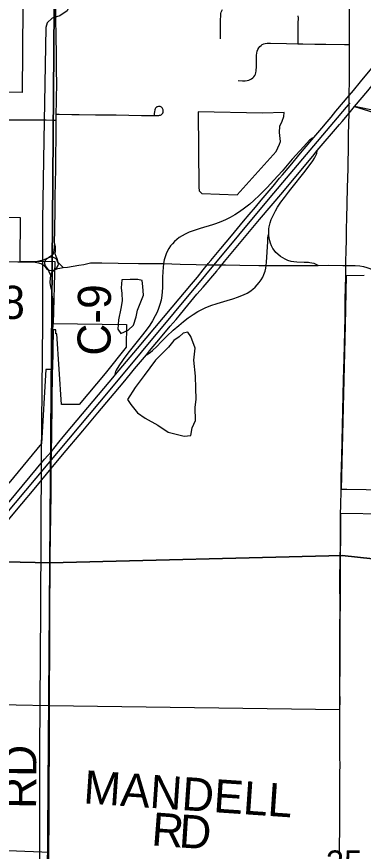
# Model space of a CAD drawing. Extents: x 0 to 34, y 0 to 22.
# Drawn here: x 6.448 to 7.043, y 18.383 to 19.815 of the extents above; entities that cross this region are included whole.
import ezdxf

# ---------------------------------------------------------------- set-up
doc = ezdxf.new("R2010")
doc.units = 0
for name, color, linetype in [('GM_X_City_Street', 7, 'Continuous'), ('GM_X_Corporation', 7, 'Continuous'), ('GM_X_County_Road', 7, 'Continuous'), ('GM_X_County_Road_Text', 7, 'Continuous'), ('GM_X_Interchange_Ramps', 7, 'Continuous'), ('GM_X_Interstate_Route', 7, 'Continuous'), ('GM_X_Minor_Lake', 7, 'Continuous'), ('GM_X_Minor_River', 7, 'Continuous'), ('GM_X_Section_Text', 7, 'Continuous'), ('GM_X_Township_Road', 7, 'Continuous'), ('GM_X_Township_Road_Text', 7, 'Continuous'), ('SH_Text', 7, 'Continuous')]:
    doc.layers.add(name, color=color, linetype=linetype)

msp = doc.modelspace()

# ---------------------------------------------------------------- linework, layer by layer
at = {"layer": 'GM_X_City_Street'}
for points in [[(6.7975, 19.7773), (6.7975, 19.7866), (6.7977, 19.809), (6.7979, 19.817), (6.7983, 19.8206), (6.7989, 19.8228), (6.8011, 19.8273)], [(6.9305, 19.8169), (6.9307, 19.8126), (6.9306, 19.8043), (6.9306, 19.7954), (6.9305, 19.7802), (6.9304, 19.7688)], [(6.828, 19.7055), (6.8354, 19.7052), (6.8399, 19.7052), (6.8431, 19.7056), (6.8462, 19.7064), (6.8486, 19.7073), (6.8509, 19.7086), (6.853, 19.7102), (6.8549, 19.7121), (6.8564, 19.7142), (6.8576, 19.7166), (6.8583, 19.7191), (6.8589, 19.7223), (6.8592, 19.7298), (6.8593, 19.7398), (6.8594, 19.7491), (6.8598, 19.7527), (6.8606, 19.7562), (6.8617, 19.759), (6.8631, 19.7616), (6.8649, 19.7639), (6.8671, 19.7659), (6.869, 19.7673), (6.8717, 19.7685), (6.8745, 19.7693), (6.8775, 19.7697), (6.8836, 19.7698), (6.911, 19.7693), (6.9304, 19.7688), (6.939, 19.7686), (6.9595, 19.7682), (6.9782, 19.7679), (7.0105, 19.7674), (7.019, 19.7673)], [(6.5157, 19.6478), (6.5203, 19.6478), (6.5425, 19.6475), (6.5549, 19.6474), (6.5829, 19.6469), (6.6186, 19.6466), (6.6403, 19.6463), (6.6621, 19.6458), (6.6823, 19.6456), (6.6884, 19.6455), (6.6915, 19.6457), (6.6929, 19.646), (6.6943, 19.6464), (6.6955, 19.647), (6.6967, 19.6478), (6.6976, 19.6488), (6.6984, 19.6499), (6.6989, 19.6512), (6.6992, 19.6525), (6.6993, 19.6539), (6.6991, 19.6552), (6.6987, 19.6566), (6.698, 19.6578), (6.6972, 19.6589), (6.6962, 19.6598), (6.695, 19.6605), (6.6937, 19.6609), (6.6924, 19.6611), (6.691, 19.6611), (6.6896, 19.6608), (6.6883, 19.6604), (6.6871, 19.6596), (6.6863, 19.6588), (6.6858, 19.6581), (6.6852, 19.657), (6.6847, 19.6552), (6.6841, 19.6521), (6.6839, 19.6492), (6.6838, 19.6462)], [(6.4255, 19.6381), (6.4609, 19.6384), (6.4984, 19.638), (6.5106, 19.6379), (6.5155, 19.6378)]]:
    msp.add_lwpolyline(points, dxfattribs=at)
at = {"layer": 'GM_X_Corporation'}
for points in [[(6.5124, 19.9044), (6.5045, 18.8781), (5.9964, 18.8894), (6.0042, 19.9104)], [(7.0187, 19.8969), (7.5413, 19.8609), (7.5285, 18.8343), (7.0065, 18.8908), (6.5045, 18.8781), (6.5124, 19.9044)], [(5.7555, 18.8946), (5.9964, 18.8894), (6.5045, 18.8781), (6.497, 17.8754), (5.4886, 17.8861), (5.4973, 18.4037), (5.5066, 18.8978)], [(6.5045, 18.8781), (7.0065, 18.8908), (7.5285, 18.8343), (7.515, 17.8763), (6.497, 17.8754)]]:
    msp.add_lwpolyline(points, close=True, dxfattribs=at)
for points in [[(6.4586, 19.9048), (6.4572, 19.685), (6.1605, 19.6876)], [(6.3826, 19.4716), (6.4539, 19.4705), (6.4531, 19.396), (6.513, 19.3953), (6.51, 19.2889), (6.6361, 19.2871), (6.6357, 19.248), (6.5996, 19.2031), (6.5552, 19.1501), (6.5247, 19.1499), (6.5163, 19.271), (6.5148, 19.2711), (6.5149, 19.2779), (6.5103, 19.278), (6.5094, 19.2097), (6.4975, 19.2097), (6.4904, 19.0829), (6.4341, 19.0148)], [(7.0811, 19.0029), (7.0142, 19.004), (7.0054, 19.0037), (7.0123, 19.286), (7.0136, 19.3711), (7.0443, 19.3716)], [(6.3894, 18.6355), (6.5036, 18.6336), (7.0023, 18.6265), (7.0043, 18.9635), (7.0803, 18.9624)]]:
    msp.add_lwpolyline(points, dxfattribs=at)
at = {"layer": 'GM_X_County_Road'}
msp.add_line((6.5155, 19.6378), (6.5157, 19.6478), dxfattribs=at)
for points in [[(6.5157, 19.6478), (6.5161, 19.6698), (6.5163, 19.705), (6.5162, 19.7182), (6.5161, 19.7331), (6.5159, 19.7492), (6.5155, 19.7828), (6.5151, 19.8102), (6.5154, 19.8494)], [(6.513, 19.4252), (6.5127, 19.4261), (6.5131, 19.4505), (6.5136, 19.4833), (6.514, 19.5094), (6.5142, 19.528), (6.5146, 19.5566), (6.5148, 19.579), (6.5153, 19.6051), (6.5154, 19.6306), (6.5155, 19.6378)], [(6.5127, 19.4261), (6.512, 19.4223), (6.5119, 19.4195), (6.5115, 19.4149), (6.5107, 19.4105), (6.5101, 19.4078), (6.508, 19.4054), (6.5024, 19.4014), (6.4989, 19.399), (6.4967, 19.397), (6.4958, 19.3953)], [(6.5128, 19.3808), (6.5155, 19.3835), (6.5174, 19.3855), (6.5187, 19.3881), (6.5195, 19.3905), (6.5189, 19.3937), (6.5169, 19.3997), (6.5153, 19.4037), (6.514, 19.4086), (6.5141, 19.4134), (6.5141, 19.4206), (6.513, 19.4252)], [(6.4958, 19.3953), (6.4955, 19.3941), (6.4953, 19.3916), (6.4964, 19.3875), (6.5015, 19.3809), (6.5026, 19.3778), (6.506, 19.3704)], [(6.506, 19.3704), (6.5076, 19.3753), (6.5089, 19.3777), (6.5128, 19.3808)], [(6.5105, 19.3277), (6.5088, 19.3382), (6.5083, 19.3438), (6.5065, 19.3517), (6.5053, 19.3589), (6.5057, 19.3664), (6.506, 19.3704)], [(6.5102, 19.2874), (6.5102, 19.2884), (6.5104, 19.3091), (6.5105, 19.3277)], [(6.5089, 19.2072), (6.5089, 19.2082), (6.5089, 19.2087), (6.5097, 19.267), (6.5099, 19.2757)], [(6.5099, 19.2757), (6.5099, 19.2767), (6.5102, 19.2874)], [(6.5038, 18.6327), (6.5038, 18.6447), (6.5044, 18.7409), (6.5043, 18.7782), (6.5046, 18.8124), (6.505, 18.8559), (6.5051, 18.8838), (6.5052, 18.8877), (6.5062, 18.9597), (6.5066, 18.9973), (6.5071, 19.0349), (6.5071, 19.0402), (6.5074, 19.0694), (6.5078, 19.0974), (6.5089, 19.2072)], [(6.5013, 18.1797), (6.5013, 18.1801), (6.5016, 18.216), (6.5029, 18.3589), (6.503, 18.382), (6.5032, 18.4397), (6.5035, 18.4925), (6.5038, 18.5639), (6.5038, 18.6327)]]:
    msp.add_lwpolyline(points, dxfattribs=at)
at = {"layer": 'GM_X_Interchange_Ramps'}
for points in [[(6.958, 19.6082), (6.9538, 19.606), (6.9521, 19.6047), (6.9501, 19.6031), (6.9406, 19.5927), (6.9335, 19.5849), (6.9208, 19.5706), (6.9034, 19.5503), (6.8893, 19.5346), (6.8774, 19.5219), (6.8647, 19.5091), (6.8547, 19.4998), (6.8477, 19.4937), (6.8389, 19.4867), (6.8303, 19.4806), (6.822, 19.4752), (6.8144, 19.4708), (6.8061, 19.4666), (6.7982, 19.4631), (6.7888, 19.4596), (6.7841, 19.458), (6.7628, 19.4517)], [(6.9651, 19.3885), (6.9619, 19.3901), (6.9581, 19.3915), (6.9546, 19.3923), (6.951, 19.393), (6.9484, 19.3932), (6.941, 19.3934), (6.9286, 19.3939), (6.9236, 19.3944), (6.9187, 19.3953), (6.9134, 19.3969), (6.9083, 19.3991), (6.9044, 19.4012), (6.9003, 19.4039), (6.8959, 19.4075), (6.8928, 19.4105), (6.8896, 19.4144), (6.8876, 19.4175), (6.8852, 19.4219), (6.8834, 19.4265), (6.8821, 19.4306), (6.8811, 19.4355), (6.8805, 19.4405), (6.8804, 19.4428), (6.8804, 19.4455), (6.8807, 19.4511), (6.8813, 19.4547), (6.8828, 19.4614), (6.8848, 19.4673), (6.8878, 19.4741), (6.8918, 19.4819), (6.8956, 19.4884), (6.901, 19.4967), (6.9073, 19.5052), (6.9142, 19.514), (6.9185, 19.5194), (6.9429, 19.5501), (6.9561, 19.568), (6.959, 19.5725), (6.9614, 19.5769), (6.9628, 19.5807), (6.9636, 19.5854)], [(6.7628, 19.4517), (6.7541, 19.4491), (6.7439, 19.4455), (6.7371, 19.4423), (6.7315, 19.4393), (6.7267, 19.4362), (6.7227, 19.4332), (6.7184, 19.4294), (6.715, 19.4257), (6.7118, 19.4218), (6.709, 19.4176), (6.7065, 19.4132), (6.7044, 19.4085), (6.7025, 19.4032), (6.701, 19.3981), (6.6998, 19.3916)], [(6.876, 19.3884), (6.8764, 19.3941), (6.8787, 19.4291), (6.8791, 19.4356), (6.8796, 19.4394), (6.8804, 19.4428)], [(6.6998, 19.3916), (6.6987, 19.3781), (6.6982, 19.3675), (6.698, 19.3507), (6.6976, 19.3433), (6.6969, 19.3371), (6.6956, 19.3291), (6.6935, 19.3213), (6.6914, 19.3148), (6.6888, 19.3084), (6.6856, 19.3017), (6.6811, 19.2935), (6.676, 19.2857), (6.6702, 19.2776), (6.6615, 19.2663), (6.6456, 19.2467), (6.6387, 19.2379), (6.6306, 19.2269), (6.6232, 19.2161), (6.6184, 19.2086), (6.6172, 19.2062), (6.6165, 19.2039), (6.6161, 19.2019), (6.6156, 19.1991)], [(6.8287, 19.3347), (6.8297, 19.335), (6.8371, 19.3379), (6.8431, 19.3406), (6.8478, 19.3438), (6.8505, 19.3456), (6.8528, 19.3476), (6.857, 19.3514), (6.8605, 19.355), (6.8642, 19.3593), (6.8671, 19.3635), (6.87, 19.3684), (6.8722, 19.3729), (6.8742, 19.3788), (6.8755, 19.3839), (6.876, 19.3884)], [(6.6703, 19.2352), (6.6731, 19.2366), (6.6774, 19.2398), (6.6807, 19.2425), (6.6883, 19.2492), (6.6959, 19.2573), (6.7056, 19.267), (6.7165, 19.2772), (6.7258, 19.2854), (6.734, 19.2922), (6.7423, 19.2987), (6.7506, 19.3043), (6.7586, 19.3092), (6.7646, 19.3124), (6.7713, 19.3156), (6.7811, 19.3196), (6.7917, 19.3233), (6.809, 19.3285), (6.8185, 19.3314), (6.8287, 19.3347)]]:
    msp.add_lwpolyline(points, dxfattribs=at)
at = {"layer": 'GM_X_Interstate_Route'}
for points in [[(7.0065, 19.6356), (7.0182, 19.6495), (7.0279, 19.6612), (7.0503, 19.6879), (7.0677, 19.7089), (7.0821, 19.7268), (7.0969, 19.7463)], [(6.4323, 18.9801), (6.4955, 19.0561), (6.5074, 19.0694), (6.5198, 19.0851), (6.5274, 19.0942), (6.5422, 19.1118), (6.6156, 19.1991), (6.6174, 19.2013), (6.6551, 19.2459), (6.7148, 19.3168), (6.7478, 19.3564), (6.7579, 19.3683), (6.7677, 19.3807), (6.7748, 19.3897), (6.7764, 19.3917), (6.7809, 19.3968), (6.7981, 19.4172), (6.8164, 19.4392), (6.837, 19.4641), (6.847, 19.476), (6.8574, 19.4884), (6.8673, 19.5004), (6.8877, 19.5247), (6.8991, 19.5379), (6.9038, 19.5436), (6.917, 19.5593), (6.935, 19.5808), (6.9546, 19.6041), (6.958, 19.6082), (6.9713, 19.624), (6.9807, 19.6349), (6.9874, 19.643), (6.9958, 19.653), (7.0186, 19.6802), (7.0258, 19.6887), (7.0382, 19.7034), (7.0605, 19.7303)], [(6.7953, 19.3838), (6.7999, 19.3893), (6.8046, 19.3949), (6.8647, 19.467), (6.9043, 19.5142), (6.9411, 19.558), (6.9563, 19.5761), (6.9636, 19.5854), (7.002, 19.6302), (7.0065, 19.6356)], [(6.5613, 19.1049), (6.5872, 19.1357), (6.6303, 19.1872), (6.643, 19.2025), (6.6501, 19.2111), (6.6703, 19.2352), (6.6757, 19.2417), (6.6944, 19.2641), (6.7113, 19.284), (6.7213, 19.2959), (6.7288, 19.305), (6.7415, 19.3203), (6.7571, 19.3389), (6.7677, 19.3511), (6.791, 19.3787), (6.7926, 19.3806), (6.7953, 19.3838)], [(5.9993, 18.429), (6.0025, 18.4329), (6.1482, 18.6079), (6.1756, 18.6411), (6.2504, 18.7308), (6.2729, 18.7581), (6.3016, 18.7925), (6.3126, 18.806), (6.342, 18.8414), (6.3988, 18.9098), (6.436, 18.9549), (6.4563, 18.9793), (6.4774, 19.0046), (6.5071, 19.0402), (6.5264, 19.0633), (6.5613, 19.1049)]]:
    msp.add_lwpolyline(points, dxfattribs=at)
at = {"layer": 'GM_X_Minor_Lake'}
for p, q in [((6.9067, 19.6507), (6.8696, 19.6497)), ((6.6279, 19.3635), (6.627, 19.3498)), ((6.7172, 19.2595), (6.7084, 19.2483))]:
    msp.add_line(p, q, dxfattribs=at)
for points in [[(6.8696, 19.6497), (6.7593, 19.6522), (6.7603, 19.5228), (6.761, 19.5163), (6.7658, 19.5121), (6.8262, 19.5094), (6.8929, 19.5841), (6.8991, 19.5965), (6.9007, 19.6011), (6.8987, 19.6167), (6.8992, 19.6273), (6.9034, 19.636), (6.9062, 19.6439), (6.9067, 19.6507)], [(6.627, 19.3498), (6.6283, 19.3403), (6.6286, 19.3278), (6.6265, 19.3146), (6.6225, 19.2953), (6.6211, 19.279), (6.6267, 19.2717), (6.6392, 19.2772), (6.648, 19.2858), (6.6528, 19.3002), (6.6552, 19.3119), (6.6653, 19.3372), (6.664, 19.3524), (6.663, 19.3623), (6.6555, 19.3643), (6.6426, 19.3641), (6.6279, 19.3635)], [(6.7084, 19.2483), (6.6858, 19.2258), (6.6666, 19.1998), (6.6508, 19.1788), (6.6381, 19.1584), (6.6436, 19.15), (6.6548, 19.1355), (6.6682, 19.1262), (6.69, 19.1145), (6.7076, 19.1025), (6.7351, 19.0957), (6.7468, 19.0967), (6.7489, 19.1096), (6.7547, 19.1224), (6.7539, 19.1445), (6.7556, 19.1592), (6.755, 19.1778), (6.7549, 19.1987), (6.7519, 19.2261), (6.7541, 19.2465), (6.7464, 19.2664), (6.7412, 19.274), (6.7336, 19.2722), (6.7264, 19.2662), (6.7172, 19.2595)]]:
    msp.add_lwpolyline(points, dxfattribs=at)
at = {"layer": 'GM_X_Minor_River'}
for points in [[(6.5788, 19.9159), (6.5676, 19.8994), (6.5595, 19.885), (6.5418, 19.8587), (6.5413, 19.8488), (6.5392, 19.836), (6.5342, 19.8254), (6.5216, 19.8164), (6.5083, 19.8124), (6.4997, 19.8047), (6.4979, 19.7966)], [(6.4979, 19.7966), (6.4943, 19.6031), (6.4917, 19.4669), (6.4921, 19.2904), (6.4898, 19.0605), (6.4887, 18.7982), (6.487, 18.555), (6.4868, 18.3599), (6.4854, 18.2509), (6.483, 18.0388), (6.4816, 17.9033)]]:
    msp.add_lwpolyline(points, dxfattribs=at)
at = {"layer": 'GM_X_Township_Road'}
for p, q in [((7.0126, 19.3885), (7.0239, 19.3884)), ((7.0046, 19.0026), (7.0046, 19.0046)), ((7.0038, 18.961), (7.0038, 18.962))]:
    msp.add_line(p, q, dxfattribs=at)
for points in [[(7.019, 19.7673), (7.019, 19.7801), (7.019, 19.7982), (7.019, 19.8118), (7.019, 19.8186), (7.019, 19.8235), (7.0191, 19.8279), (7.0191, 19.8322), (7.0191, 19.8365), (7.0191, 19.8378), (7.0191, 19.8427), (7.0191, 19.847), (7.0191, 19.8488), (7.0191, 19.8519), (7.0193, 19.8643), (7.0194, 19.8724)], [(7.0126, 19.3885), (7.0128, 19.3981), (7.0131, 19.4107), (7.0136, 19.4354), (7.014, 19.4522), (7.0145, 19.4684), (7.0158, 19.5213), (7.0165, 19.5549), (7.0167, 19.5641), (7.0171, 19.5886), (7.0176, 19.6124), (7.0182, 19.6495), (7.0186, 19.6802), (7.0191, 19.7072), (7.0191, 19.7192), (7.0191, 19.7256), (7.0191, 19.7363), (7.019, 19.7481), (7.019, 19.7597), (7.019, 19.7673)], [(6.2247, 19.3845), (6.2307, 19.385), (6.2397, 19.387), (6.2507, 19.39), (6.259, 19.3918), (6.2674, 19.393), (6.2771, 19.394), (6.3229, 19.3961), (6.3404, 19.3959), (6.3578, 19.396), (6.3821, 19.3956), (6.4043, 19.3952), (6.4225, 19.3949), (6.4499, 19.3946), (6.4517, 19.3946), (6.4527, 19.3946)], [(6.4527, 19.3946), (6.4648, 19.3944), (6.4796, 19.3942)], [(6.5276, 19.3846), (6.5224, 19.39), (6.5201, 19.3921), (6.5189, 19.3937), (6.5179, 19.395), (6.5163, 19.3984), (6.5142, 19.4005), (6.5108, 19.4021), (6.5073, 19.4025), (6.5024, 19.4014), (6.4995, 19.4004), (6.493, 19.3973), (6.4856, 19.3959), (6.4796, 19.3942)], [(6.4796, 19.3942), (6.485, 19.3926), (6.4911, 19.3911), (6.4946, 19.3882), (6.496, 19.3865), (6.4978, 19.3843), (6.4995, 19.3823), (6.5015, 19.3809), (6.5039, 19.3802), (6.507, 19.3798), (6.5128, 19.3808)], [(6.5276, 19.3846), (6.5351, 19.3855), (6.5445, 19.3871), (6.5544, 19.3889), (6.5629, 19.3898), (6.5744, 19.3928)], [(6.5744, 19.3928), (6.5937, 19.3927), (6.6216, 19.3923), (6.657, 19.3918), (6.6763, 19.3917), (6.6998, 19.3916)], [(6.6998, 19.3916), (6.7284, 19.3906), (6.7556, 19.3901), (6.7748, 19.3897), (6.7999, 19.3893), (6.8062, 19.3892), (6.831, 19.3888), (6.8633, 19.3885), (6.876, 19.3884)], [(6.5128, 19.3808), (6.514, 19.3812), (6.5185, 19.3829), (6.522, 19.3838), (6.5276, 19.3846)], [(6.876, 19.3884), (6.908, 19.3882), (6.9552, 19.3883), (6.9651, 19.3885)], [(6.9651, 19.3885), (6.9825, 19.3888), (7.0075, 19.3885), (7.0126, 19.3885)], [(7.0125, 19.3694), (7.0126, 19.3843), (7.0126, 19.3885)], [(7.0239, 19.3884), (7.0287, 19.3884), (7.0366, 19.3879), (7.0429, 19.3867), (7.0487, 19.3849), (7.0539, 19.3829), (7.0589, 19.3806), (7.0698, 19.3747), (7.0749, 19.3722), (7.0789, 19.3706)], [(7.0046, 19.0046), (7.005, 19.0246), (7.0058, 19.0607), (7.009, 19.1919), (7.0101, 19.2286), (7.0106, 19.2517), (7.011, 19.2759), (7.0115, 19.2992), (7.0118, 19.3301), (7.0122, 19.3507), (7.0125, 19.3694)], [(7.0038, 18.962), (7.004, 18.9764), (7.0046, 19.0026)], [(7.0025, 18.6198), (7.0025, 18.6259), (7.0028, 18.6427), (7.0026, 18.6558), (7.0027, 18.667), (7.0026, 18.6825), (7.0026, 18.6974), (7.0025, 18.7677), (7.0028, 18.7957), (7.0028, 18.8056), (7.0029, 18.8174), (7.0027, 18.8318), (7.0027, 18.8628), (7.0028, 18.8715), (7.0034, 18.9229), (7.0035, 18.9331), (7.0038, 18.961)], [(7.0027, 18.3472), (7.0026, 18.3511), (7.0025, 18.3629), (7.0021, 18.3978), (7.0023, 18.4152), (7.0024, 18.4425), (7.0024, 18.4544), (7.0025, 18.4643), (7.0023, 18.4836), (7.0026, 18.5047), (7.0026, 18.5172), (7.0029, 18.5314), (7.0027, 18.5439), (7.0027, 18.5588), (7.0026, 18.5799), (7.0026, 18.6054), (7.0025, 18.6198)], [(6.0725, 18.3922), (6.0744, 18.3924), (6.0774, 18.3927), (6.09, 18.3926), (6.1395, 18.3914), (6.1452, 18.3913), (6.18, 18.3905), (6.2204, 18.3894), (6.2581, 18.3887), (6.2959, 18.3877), (6.3915, 18.3851), (6.4475, 18.3838), (6.4906, 18.3823), (6.503, 18.382)]]:
    msp.add_lwpolyline(points, dxfattribs=at)
at = {"layer": 'SH_Text'}
msp.add_lwpolyline([(3.9929, 16.0574), (4.3255, 16.5268), (4.5753, 16.8408), (4.8525, 17.1076), (5.0171, 17.2706), (5.117, 17.382), (5.2403, 17.5277), (5.4467, 17.7775), (5.7427, 18.1382), (6.1773, 18.6589), (6.374, 18.8962), (6.608, 19.1749), (6.883, 19.5049), (7.0202, 19.6674)], dxfattribs=at)
msp.add_lwpolyline([(7.0279, 19.6612), (9.327, 18.9498), (9.327, 19.1946)], close=True, dxfattribs=at)

# ---------------------------------------------------------------- texts
at = {"layer": 'GM_X_County_Road_Text'}
for s, rotation, p in [('C-9', 89.5566, (6.6087, 19.2334)), ('RD', 89.5113, (6.481, 18.4559))]:
    msp.add_text(s, height=0.05682, rotation=rotation, dxfattribs=at).set_placement(p)
at = {"layer": 'GM_X_Section_Text'}
msp.add_text('35', height=0.04186, rotation=0, dxfattribs=at).set_placement((6.9787, 18.3428))
at = {"layer": 'GM_X_Township_Road_Text'}
for s, height, rotation, p in [('T-68', 0.05682, 359.2966, (6.3053, 19.2983)), ('MANDELL', 0.05682, 356.1026, (6.5613, 18.4657)), ('R', 0.0568, 355.6205, (6.6779, 18.3936)), ('D', 0.0568, 356.3329, (6.7252, 18.39))]:
    msp.add_text(s, height=height, rotation=rotation, dxfattribs=at).set_placement(p)

doc.saveas('drawing.dxf')
